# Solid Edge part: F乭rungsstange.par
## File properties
Username: bmolnar
Dokumentum tartalom típus: 0
Author: bmolnar
Last saved by: bmolnar
Revision: 78
Sűrűség: 0,000 kg/m^3
Pontosság: 0,990
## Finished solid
Body 1: solid body, 8 faces, 7 edges, 5 vertices.
  Faces by surface: cone 4, cylinder 2, plane 2
  Edges by curve: circle 7
Bounding box of the edges (mm): 5.000 x 5.000 x 48.000, from (-2.5, -2.5, -29) to (2.5, 2.5, 19).
Cylindrical faces by radius (mm): R1.2295 x1, R2.5 x1
Conical faces (half-angle, radius in mm at the cone's reference point): 45 deg R1.3295 x1, 45 deg R2.25 x1, 45 deg R2.4 x1, 59 deg R0.6148 x1
Planar faces by outward normal: +z 1, -z 1
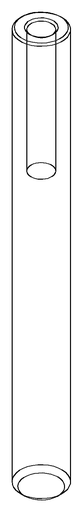
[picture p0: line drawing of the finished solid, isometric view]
